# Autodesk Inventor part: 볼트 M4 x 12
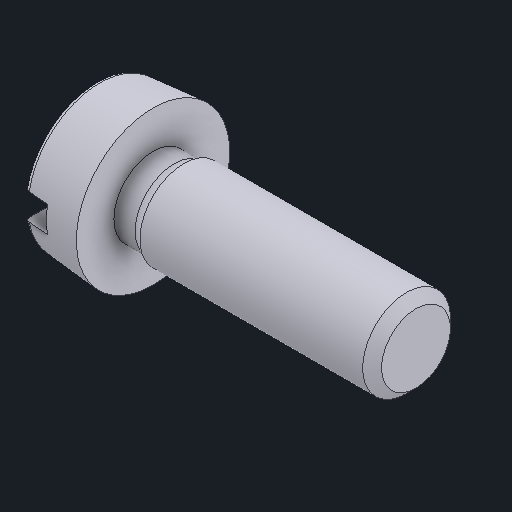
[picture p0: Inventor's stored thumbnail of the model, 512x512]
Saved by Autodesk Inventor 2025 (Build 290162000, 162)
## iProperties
Created: 2025-08
Part Number: 볼트 M4 x 12
Material: 강철, 연강
Description: 6각머리 태핑 나사
Document SubType Name: Modeling
Designer: infra15
Density: 7.85 g/cm^3
Appearance: 기본값
Author: jhkim
Sending System: Autodesk Inventor 2026
Preprocessor: ST-DEVELOPER v20.1
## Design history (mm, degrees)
feature "Solid1"
node "솔리드1"
